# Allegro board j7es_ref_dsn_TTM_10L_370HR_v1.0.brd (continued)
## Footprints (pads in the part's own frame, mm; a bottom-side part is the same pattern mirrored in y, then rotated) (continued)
HTSSOP14_TPS1H100-Q1_180X200_1-2
  rect 1.6x0.305 smd: 1(-2.8,1.95) 2(-2.8,1.3) 3(-2.8,0.65) 4(-2.8,0) 5(-2.8,-0.65) 6(-2.8,-1.3) 7(-2.8,-1.95) 8(2.8,-1.95) 9(2.8,-1.3) 10(2.8,-0.65) 11(2.8,0) 12(2.8,0.65) 13(2.8,1.3) 14(2.8,1.95)
  rect 3.404x5.004 smd: 15(0,0)
IND2-7030D
  rect 2.032x3.81 smd: 1(-2.921,0) 2(2.921,0)
IND2-ATCA-06
  round 2.286 hole 1.219: 1(-7.493,0) 2(7.493,0)
IND2-LQH3N
  rect 1.397x3.048 smd: 1(-1.27,0) 2(1.27,0)
IND1008_1-2
  rect 1.194x2.21 smd: 1(-1.1,0) 2(1.1,0)
IND2520-40X80
  rect 1.016x2.032 smd: 1(-1.118,0) 2(1.118,0)
IND-DFEG10040
  rect 2.997x3.429 smd: 1(-4.445,0) 2(4.445,0)
IND-IHLP2020
  rect 1.778x2.794 smd: 1(-2.413,0) 2(2.413,0)
IND-IHLP5050
  rect 2.921x5.385 smd: 1(-5.588,0) 2(5.588,0)
IND-IHLP-COMBO
  custom 0.724x0.724 smd: 1(-3.607,0) 2(3.607,0)
IND-MSS7341
  rect 2.54x7.112 smd: 1(-2.286,0) 2(2.286,0)
JMP402-25
  rect 0.635x0.635 smd: 1(-0.508,0)
  round 0.635 smd: 2(0.508,0) 3(1.524,0)
JUMP1X2-6040
  rect 1.524x1.524 hole 1.016: 1(0,0)
  round 1.524 hole 1.016: 2(0,-2.54)
L603-35X45
  oval 0.889x1.143 smd: 1(-0.762,0) 2(0.762,0)
LED1206-59X59
  rect 1.499x1.499 smd: 1(-1.753,0) 2(1.753,0)
MHP93-200
  round 5.08 hole 2.362: 1(0,0)
MOLEX-34826-0124
  round 1.524 hole 0.991: 1(-7.01,1.295) 2(-5.004,1.295) 3(5.004,1.295) 4(7.01,1.295) 5(-7.01,-0.914) 6(-5.004,-0.914) 7(-2.997,-0.914) 8(-0.991,-0.914) 9(0.991,-0.914) 10(2.997,-0.914) 11(5.004,-0.914) 12(7.01,-0.914)
  round 3.556 hole 2.54: 13(-9.855,0) 14(9.855,0)
OSC4_ASDMB_100X85_SMD_0-9
  rect 0.66x0.864 smd: 1(-0.825,-0.775) 2(0.825,-0.775) 3(0.825,0.775) 4(-0.825,0.775)
PWP16-14X70-PAD
  oval 0.356x1.778 smd: 1(-2.276,-2.987) 2(-1.626,-2.987) 3(-0.975,-2.987) 4(-0.325,-2.987) 5(0.325,-2.987) 6(0.975,-2.987) 7(1.626,-2.987) 8(2.276,-2.987) 9(2.276,2.987) 10(1.626,2.987) 11(0.975,2.987) 12(0.325,2.987) 13(-0.325,2.987) 14(-0.975,2.987) 15(-1.626,2.987) 16(-2.276,2.987)
  rect 4.572x3.048 smd: 17(0,0)
PWP28-14X70
  oval 0.356x1.778 smd: 1(-4.227,-2.921) 2(-3.576,-2.921) 3(-2.926,-2.921) 4(-2.276,-2.921) 5(-1.626,-2.921) 6(-0.975,-2.921) 7(-0.325,-2.921) 8(0.325,-2.921) 9(0.975,-2.921) 10(1.626,-2.921) 11(2.276,-2.921) 12(2.926,-2.921) 13(3.576,-2.921) 14(4.227,-2.921) 15(4.227,2.921) 16(3.576,2.921) 17(2.926,2.921) 18(2.276,2.921) 19(1.626,2.921) 20(0.975,2.921) 21(0.325,2.921) 22(-0.325,2.921) 23(-0.975,2.921) 24(-1.626,2.921) 25(-2.276,2.921) 26(-2.926,2.921) 27(-3.576,2.921) 28(-4.227,2.921)
  rect 7.62x2.54 smd: 29(0,0)
PWR-Q5A-SLPS319
  rect 0.711x1.397 smd: 1(-1.905,0) 2(-0.635,0) 3(0.635,0) 4(1.905,0)
  custom 1.111x1.111 smd: 5(0,2.781)
QFN64_19-68_360X360_0-9_EP6
  rect 0.838x0.305 smd: 1(-4.5,3.75) 2(-4.5,3.25) 3(-4.5,2.75) 4(-4.5,2.25) 5(-4.5,1.75) 6(-4.5,1.25) 7(-4.5,0.75) 8(-4.5,0.25) 9(-4.5,-0.25) 10(-4.5,-0.75) 11(-4.5,-1.25) 12(-4.5,-1.75) 13(-4.5,-2.25) 14(-4.5,-2.75) 15(-4.5,-3.25) 16(-4.5,-3.75) 33(4.5,-3.75) 34(4.5,-3.25) 35(4.5,-2.75) 36(4.5,-2.25) 37(4.5,-1.75) 38(4.5,-1.25) 39(4.5,-0.75) 40(4.5,-0.25) 41(4.5,0.25) 42(4.5,0.75) 43(4.5,1.25) 44(4.5,1.75) 45(4.5,2.25) 46(4.5,2.75) 47(4.5,3.25) 48(4.5,3.75)
  rect 0.305x0.838 smd: 17(-3.75,-4.5) 18(-3.25,-4.5) 19(-2.75,-4.5) 20(-2.25,-4.5) 21(-1.75,-4.5) 22(-1.25,-4.5) 23(-0.75,-4.5) 24(-0.25,-4.5) 25(0.25,-4.5) 26(0.75,-4.5) 27(1.25,-4.5) 28(1.75,-4.5) 29(2.25,-4.5) 30(2.75,-4.5) 31(3.25,-4.5) 32(3.75,-4.5) 49(3.75,4.5) 50(3.25,4.5) 51(2.75,4.5) 52(2.25,4.5) 53(1.75,4.5) 54(1.25,4.5) 55(0.75,4.5) 56(0.25,4.5) 57(-0.25,4.5) 58(-0.75,4.5) 59(-1.25,4.5) 60(-1.75,4.5) 61(-2.25,4.5) 62(-2.75,4.5) 63(-3.25,4.5) 64(-3.75,4.5)
  rect 5.994x5.994 smd: 65(0,0)
QSH-030-01-F
  round 0.508 hole 1.016 unplated: (-10.061,2.667) (10.061,2.667)
  rect 0.279x2.273 smd: 1(-7.249,-2.865) 2(-7.249,2.865) 3(-6.749,-2.865) 4(-6.749,2.865) 5(-6.248,-2.865) 6(-6.248,2.865) 7(-5.748,-2.865) 8(-5.748,2.865) 9(-5.248,-2.865) 10(-5.248,2.865) 11(-4.75,-2.865) 12(-4.75,2.865) 13(-4.249,-2.865) 14(-4.249,2.865) 15(-3.749,-2.865) 16(-3.749,2.865) 17(-3.249,-2.865) 18(-3.249,2.865) 19(-2.748,-2.865) 20(-2.748,2.865) 21(-2.25,-2.865) 22(-2.25,2.865) 23(-1.75,-2.865) 24(-1.75,2.865) 25(-1.25,-2.865) 26(-1.25,2.865) 27(-0.749,-2.865) 28(-0.749,2.865) 29(-0.249,-2.865) 30(-0.249,2.865) 31(0.249,-2.865) 32(0.249,2.865) 33(0.749,-2.865) 34(0.749,2.865) 35(1.25,-2.865) 36(1.25,2.865) 37(1.75,-2.865) 38(1.75,2.865) 39(2.25,-2.865) 40(2.25,2.865) 41(2.748,-2.865) 42(2.748,2.865) 43(3.249,-2.865) 44(3.249,2.865) 45(3.749,-2.865) 46(3.749,2.865) 47(4.249,-2.865) 48(4.249,2.865) 49(4.75,-2.865) 50(4.75,2.865) 51(5.248,-2.865) 52(5.248,2.865) 53(5.748,-2.865) 54(5.748,2.865) 55(6.248,-2.865) 56(6.248,2.865) 57(6.749,-2.865) 58(6.749,2.865) 59(7.249,-2.865) 60(7.249,2.865)
  rect 2.54x0.432 smd: 61(-8.065,0) 64(8.065,0)
  rect 4.699x0.432 smd: 62(-3.175,0) 63(3.175,0)
R201-6P6SPC
  rect 0.47x0.381 smd: 1(-0.343,0) 2(0.343,0)
R402-25
  round 0.635 smd: 1(-0.508,0) 2(0.508,0)
R603-35X45
  oval 0.889x1.143 smd: 1(-0.762,0) 2(0.762,0)
R0612
  rect 3.175x0.889 smd: 1(0,-0.813) 2(0,0.813)
R1206-40X70
  oval 1.016x1.778 smd: 1(-1.524,0) 2(1.524,0)
RES0201_0-5
  rect 0.457x0.432 smd: 1(-0.33,0) 2(0.33,0)
RES0402_0-5
  rect 0.483x0.508 smd: 1(-0.42,0) 2(0.42,0)
RES0402_1
  rect 0.559x0.635 smd: 1(-0.49,0) 2(0.49,0)
RGE24-11X28-4MM
  rect 0.711x0.279 smd: 1(-1.905,1.245) 2(-1.905,0.747) 3(-1.905,0.249) 4(-1.905,-0.249) 5(-1.905,-0.747) 6(-1.905,-1.245) 13(1.905,-1.245) 14(1.905,-0.747) 15(1.905,-0.249) 16(1.905,0.249) 17(1.905,0.747) 18(1.905,1.245)
  rect 0.279x0.711 smd: 7(-1.245,-1.905) 8(-0.747,-1.905) 9(-0.249,-1.905) 10(0.249,-1.905) 11(0.747,-1.905) 12(1.245,-1.905) 19(1.245,1.905) 20(0.747,1.905) 21(0.249,1.905) 22(-0.249,1.905) 23(-0.747,1.905) 24(-1.245,1.905)
  rect 2.464x2.464 smd: 25(0,0)
RND36-24X10
  oval 0.254x0.61 smd: 1(-2.002,-2.896) 2(-1.501,-2.896) 3(-1.001,-2.896) 4(-0.5,-2.896) 5(0,-2.896) 6(0.498,-2.896) 7(0.998,-2.896) 8(1.499,-2.896) 9(1.999,-2.896) 19(2.002,2.896) 20(1.501,2.896) 21(1.001,2.896) 22(0.5,2.896) 23(0,2.896) 24(-0.498,2.896) 25(-0.998,2.896) 26(-1.499,2.896) 27(-1.999,2.896)
  oval 0.61x0.254 smd: 10(2.896,-2.002) 11(2.896,-1.501) 12(2.896,-1.001) 13(2.896,-0.5) 14(2.896,0) 15(2.896,0.498) 16(2.896,0.998) 17(2.896,1.499) 18(2.896,1.999) 28(-2.896,1.999) 29(-2.896,1.499) 30(-2.896,0.998) 31(-2.896,0.498) 32(-2.896,0) 33(-2.896,-0.5) 34(-2.896,-1.001) 35(-2.896,-1.501) 36(-2.896,-2.002)
  rect 3.81x3.81 smd: 37(0,0)
RTD0064F
  rect 0.6x0.25 smd: 1(-4.4,3.75) 2(-4.4,3.25) 3(-4.4,2.75) 4(-4.4,2.25) 5(-4.4,1.75) 6(-4.4,1.25) 7(-4.4,0.75) 8(-4.4,0.25) 9(-4.4,-0.25) 10(-4.4,-0.75) 11(-4.4,-1.25) 12(-4.4,-1.75) 13(-4.4,-2.25) 14(-4.4,-2.75) 15(-4.4,-3.25) 16(-4.4,-3.75) 33(4.4,-3.75) 34(4.4,-3.25) 35(4.4,-2.75) 36(4.4,-2.25) 37(4.4,-1.75) 38(4.4,-1.25) 39(4.4,-0.75) 40(4.4,-0.25) 41(4.4,0.25) 42(4.4,0.75) 43(4.4,1.25) 44(4.4,1.75) 45(4.4,2.25) 46(4.4,2.75) 47(4.4,3.25) 48(4.4,3.75)
  rect 0.25x0.6 smd: 17(-3.75,-4.4) 18(-3.25,-4.4) 19(-2.75,-4.4) 20(-2.25,-4.4) 21(-1.75,-4.4) 22(-1.25,-4.4) 23(-0.75,-4.4) 24(-0.25,-4.4) 25(0.25,-4.4) 26(0.75,-4.4) 27(1.25,-4.4) 28(1.75,-4.4) 29(2.25,-4.4) 30(2.75,-4.4) 31(3.25,-4.4) 32(3.75,-4.4) 49(3.75,4.4) 50(3.25,4.4) 51(2.75,4.4) 52(2.25,4.4) 53(1.75,4.4) 54(1.25,4.4) 55(0.75,4.4) 56(0.25,4.4) 57(-0.25,4.4) 58(-0.75,4.4) 59(-1.25,4.4) 60(-1.75,4.4) 61(-2.25,4.4) 62(-2.75,4.4) 63(-3.25,4.4) 64(-3.75,4.4)
  rect 5.75x5.75 smd: 65(0,0)
RVC20
  rect 0.279x0.711 smd: 1(-1.245,-1.422) 2(-0.747,-1.422) 3(-0.249,-1.422) 4(0.249,-1.422) 5(0.747,-1.422) 6(1.245,-1.422) 11(1.245,1.422) 12(0.747,1.422) 13(0.249,1.422) 14(-0.249,1.422) 15(-0.747,1.422) 16(-1.245,1.422)
  rect 0.711x0.279 smd: 7(1.905,-0.747) 8(1.905,-0.249) 9(1.905,0.249) 10(1.905,0.747) 17(-1.905,0.747) 18(-1.905,0.249) 19(-1.905,-0.249) 20(-1.905,-0.747)
  rect 2.388x1.6 smd: 21(0,0)
SMA2-78SQ
  rect 1.981x1.981 smd: 1(-2.007,0) 2(2.007,0)
SMC-80X128
  rect 2.032x3.251 smd: 1(-3.124,0) 2(3.124,0)
SO8-25X75-295
  oval 0.635x2.54 smd: 1(-1.905,-3.086) 2(-0.635,-3.086) 3(0.635,-3.086) 4(1.905,-3.086) 5(1.905,3.086) 6(0.635,3.086) 7(-0.635,3.086) 8(-1.905,3.086)
SO14-25X75
  oval 0.635x1.905 smd: 1(-3.81,-2.794) 2(-2.54,-2.794) 3(-1.27,-2.794) 4(0,-2.794) 5(1.27,-2.794) 6(2.54,-2.794) 7(3.81,-2.794) 8(3.81,2.794) 9(2.54,2.794) 10(1.27,2.794) 11(0,2.794) 12(-1.27,2.794) 13(-2.54,2.794) 14(-3.81,2.794)
SOD323
  rect 1.092x0.508 smd: 1(-1.194,0) 2(1.194,0)
SOD523
  rect 0.762x0.381 smd: 1(0.838,0) 2(-0.838,0)
SOT23-5
  rect 0.635x1.016 smd: 1(-0.953,-1.295) 2(0,-1.295) 3(0.953,-1.295) 4(0.953,1.295) 5(-0.953,1.295)
SOT23-28X44-GSD
  rect 0.711x1.118 smd: D(0,1.067) G(-0.965,-1.067) S(0.965,-1.067)
SOT23-123_1-2
  rect 0.838x0.61 smd: 1(-1.05,0.95) 2(-1.05,-0.95) 3(1.05,0)
SOT363-16X45
  rect 0.406x0.635 smd: 1(-0.65,-0.978) 2(0,-0.978) 3(0.65,-0.978) 4(0.65,0.978) 5(0,0.978) 6(-0.65,0.978)
SSOP-16
  oval 0.356x1.778 smd: 1(-2.223,-2.692) 2(-1.587,-2.692) 3(-0.953,-2.692) 4(-0.318,-2.692) 5(0.318,-2.692) 6(0.953,-2.692) 7(1.587,-2.692) 8(2.223,-2.692) 9(2.223,2.692) 10(1.587,2.692) 11(0.953,2.692) 12(0.318,2.692) 13(-0.318,2.692) 14(-0.953,2.692) 15(-1.587,2.692) 16(-2.223,2.692)
SW4-7914G
  rect 1.27x1.778 smd: 1(1.27,2.769) 2(1.27,-2.769) 3(-1.27,2.769) 4(-1.27,-2.769)
TP1-18RD8
  round 0.457 hole 0.203: 1(0,0)
TP1-70X135
  rect 2.286x3.937 smd: 1(0,0)
TP40_SMD
  round 1.016 smd: 1(0,0)
TP-30RD13
  round 0.762 hole 0.33: 1(0,0)
TPBGA24_39-37_240X320_1-2
  round 0.356 smd: A2(-1,2) A3(0,2) A4(1,2) A5(2,2) B1(-2,1) B2(-1,1) B3(0,1) B4(1,1) B5(2,1) C1(-2,0) C2(-1,0) C3(0,0) C4(1,0) C5(2,0) D1(-2,-1) D2(-1,-1) D3(0,-1) D4(1,-1) D5(2,-1) E1(-2,-2) E2(-1,-2) E3(0,-2) E4(1,-2) E5(2,-2)
TSDSON8
  custom 0.248x0.248 smd: 1(-0.33,-1.499)
  rect 0.356x1.016 smd: 4(0.978,-1.486)
  custom 0.572x0.572 smd: 5(0,0.673)
unnamed#2
  round 6.223 hole 6.35 unplated: (0,0)
unnamed#3
  rect 0.508x0.305 smd: 1(-0.612,0.275) 2(-0.612,-0.275) 3(0.612,-0.275) 4(0.612,0.275)
unnamed#4
  rect 0.483x0.508 smd: 1(-0.42,0) 2(0.42,0)
VQFN56_19-68_320X320_0-9_EP6
  rect 0.787x0.305 smd: 1(-4,3.25) 2(-4,2.75) 3(-4,2.25) 4(-4,1.75) 5(-4,1.25) 6(-4,0.75) 7(-4,0.25) 8(-4,-0.25) 9(-4,-0.75) 10(-4,-1.25) 11(-4,-1.75) 12(-4,-2.25) 13(-4,-2.75) 14(-4,-3.25) 29(4,-3.25) 30(4,-2.75) 31(4,-2.25) 32(4,-1.75) 33(4,-1.25) 34(4,-0.75) 35(4,-0.25) 36(4,0.25) 37(4,0.75) 38(4,1.25) 39(4,1.75) 40(4,2.25) 41(4,2.75) 42(4,3.25)
  rect 0.305x0.787 smd: 15(-3.25,-4) 16(-2.75,-4) 17(-2.25,-4) 18(-1.75,-4) 19(-1.25,-4) 20(-0.75,-4) 21(-0.25,-4) 22(0.25,-4) 23(0.75,-4) 24(1.25,-4) 25(1.75,-4) 26(2.25,-4) 27(2.75,-4) 28(3.25,-4) 43(3.25,4) 44(2.75,4) 45(2.25,4) 46(1.75,4) 47(1.25,4) 48(0.75,4) 49(0.25,4) 50(-0.25,4) 51(-0.75,4) 52(-1.25,4) 53(-1.75,4) 54(-2.25,4) 55(-2.75,4) 56(-3.25,4)
  rect 5.588x5.588 smd: 57(0,0)
WFBGA200_MT53DDS_400X570_1
  round 0.356 smd: A1(-4.4,6.825) A2(-3.6,6.825) A3(-2.8,6.825) A4(-2,6.825) A5(-1.2,6.825) A8(1.2,6.825) A9(2,6.825) A10(2.8,6.825) A11(3.6,6.825) A12(4.4,6.825) AA1(-4.4,-6.175) AA2(-3.6,-6.175) AA3(-2.8,-6.175) AA4(-2,-6.175) AA5(-1.2,-6.175) AA8(1.2,-6.175) AA9(2,-6.175) AA10(2.8,-6.175) AA11(3.6,-6.175) AA12(4.4,-6.175) AB1(-4.4,-6.825) AB2(-3.6,-6.825) AB3(-2.8,-6.825) AB4(-2,-6.825) AB5(-1.2,-6.825) AB8(1.2,-6.825) AB9(2,-6.825) AB10(2.8,-6.825) AB11(3.6,-6.825) AB12(4.4,-6.825) B1(-4.4,6.175) B2(-3.6,6.175) B3(-2.8,6.175) B4(-2,6.175) B5(-1.2,6.175) B8(1.2,6.175) B9(2,6.175) B10(2.8,6.175) B11(3.6,6.175) B12(4.4,6.175) C1(-4.4,5.525) C2(-3.6,5.525) C3(-2.8,5.525) C4(-2,5.525) C5(-1.2,5.525) C8(1.2,5.525) C9(2,5.525) C10(2.8,5.525) C11(3.6,5.525) C12(4.4,5.525) D1(-4.4,4.875) D2(-3.6,4.875) D3(-2.8,4.875) D4(-2,4.875) D5(-1.2,4.875) D8(1.2,4.875) D9(2,4.875) D10(2.8,4.875) D11(3.6,4.875) D12(4.4,4.875) E1(-4.4,4.225) E2(-3.6,4.225) E3(-2.8,4.225) E4(-2,4.225) E5(-1.2,4.225) E8(1.2,4.225) E9(2,4.225) E10(2.8,4.225) E11(3.6,4.225) E12(4.4,4.225) F1(-4.4,3.575) F2(-3.6,3.575) F3(-2.8,3.575) F4(-2,3.575) F5(-1.2,3.575) F8(1.2,3.575) F9(2,3.575) F10(2.8,3.575) F11(3.6,3.575) F12(4.4,3.575) G1(-4.4,2.925) G2(-3.6,2.925) G3(-2.8,2.925) G4(-2,2.925) G5(-1.2,2.925) G8(1.2,2.925) G9(2,2.925) G10(2.8,2.925) G11(3.6,2.925) G12(4.4,2.925) H1(-4.4,2.275) H2(-3.6,2.275) H3(-2.8,2.275) H4(-2,2.275) H5(-1.2,2.275) H8(1.2,2.275) H9(2,2.275) H10(2.8,2.275) H11(3.6,2.275) H12(4.4,2.275) J1(-4.4,1.625) J2(-3.6,1.625) J3(-2.8,1.625) J4(-2,1.625) J5(-1.2,1.625) J8(1.2,1.625) J9(2,1.625) J10(2.8,1.625) J11(3.6,1.625) J12(4.4,1.625) K1(-4.4,0.975) K2(-3.6,0.975) K3(-2.8,0.975) K4(-2,0.975) K5(-1.2,0.975) K8(1.2,0.975) K9(2,0.975) K10(2.8,0.975) K11(3.6,0.975) K12(4.4,0.975) N1(-4.4,-0.975) N2(-3.6,-0.975) N3(-2.8,-0.975) N4(-2,-0.975) N5(-1.2,-0.975) N8(1.2,-0.975) N9(2,-0.975) N10(2.8,-0.975) N11(3.6,-0.975) N12(4.4,-0.975) P1(-4.4,-1.625) P2(-3.6,-1.625) P3(-2.8,-1.625) P4(-2,-1.625) P5(-1.2,-1.625) P8(1.2,-1.625) P9(2,-1.625) P10(2.8,-1.625) P11(3.6,-1.625) P12(4.4,-1.625) R1(-4.4,-2.275) R2(-3.6,-2.275) R3(-2.8,-2.275) R4(-2,-2.275) R5(-1.2,-2.275) R8(1.2,-2.275) R9(2,-2.275) R10(2.8,-2.275) R11(3.6,-2.275) R12(4.4,-2.275) T1(-4.4,-2.925) T2(-3.6,-2.925) T3(-2.8,-2.925) T4(-2,-2.925) T5(-1.2,-2.925) T8(1.2,-2.925) T9(2,-2.925) T10(2.8,-2.925) T11(3.6,-2.925) T12(4.4,-2.925) U1(-4.4,-3.575) U2(-3.6,-3.575) U3(-2.8,-3.575) U4(-2,-3.575) U5(-1.2,-3.575) U8(1.2,-3.575) U9(2,-3.575) U10(2.8,-3.575) U11(3.6,-3.575) U12(4.4,-3.575) V1(-4.4,-4.225) V2(-3.6,-4.225) V3(-2.8,-4.225) V4(-2,-4.225) V5(-1.2,-4.225) V8(1.2,-4.225) V9(2,-4.225) V10(2.8,-4.225) V11(3.6,-4.225) V12(4.4,-4.225) W1(-4.4,-4.875) W2(-3.6,-4.875) W3(-2.8,-4.875) W4(-2,-4.875) W5(-1.2,-4.875) W8(1.2,-4.875) W9(2,-4.875) W10(2.8,-4.875) W11(3.6,-4.875) W12(4.4,-4.875) Y1(-4.4,-5.525) Y2(-3.6,-5.525) Y3(-2.8,-5.525) Y4(-2,-5.525) Y5(-1.2,-5.525) Y8(1.2,-5.525) Y9(2,-5.525) Y10(2.8,-5.525) Y11(3.6,-5.525) Y12(4.4,-5.525)
WSON8_19-68_80X80_0-8
  rect 0.711x0.305 smd: 1(-1.05,0.75) 2(-1.05,0.25) 3(-1.05,-0.25) 4(-1.05,-0.75) 5(1.05,-0.75) 6(1.05,-0.25) 7(1.05,0.25) 8(1.05,0.75)
  rect 0.991x1.702 smd: 9(0,0)
XTAL4-ABM11
  rect 0.889x0.813 smd: 1(-0.711,-0.559) 2(0.711,-0.559) 3(0.711,0.559) 4(-0.711,0.559)
XTAL4_ABM10W_100X80_SMD_0-6
  rect 1.194x0.838 smd: 1(-0.813,-0.6) 2(0.813,-0.6) 3(0.813,0.6) 4(-0.813,0.6)
XTAL_ABS07AIG_130X60_SMD_0-9
  rect 0.991x1.803 smd: 1(-1.275,0) 2(1.275,0)
XTAL_ECS-32_130X60_SMD_0-9
  rect 1.118x1.905 smd: 1(-1.25,0) 2(1.25,0)

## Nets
1V8_RSTOUTN: R1192.1 U1017.M5(RSTN) U1033.4(O)
DGND: C26.2 C27.2 C28.2 C29.2 C30.2 C31.2 C32.2(GND) C33.2(GND) C34.2 C35.2 C37.2(GND) C38.2(GND) C41.2(GND) C42.2(GND) C43.2 C44.2 C45.2 C46.2 C47.2 C48.2 C49.2 C50.2 C53.2(GND) C54.2(GND) C55.2 C56.2 C57.2(GND) C58.2(GND) C59.2(GND) C60.2 C61.2 C62.2 C63.2 C64.2(GND) C65.2(GND) C66.2(GND) C67.2(GND) C68.2(GND) C69.2(GND) C70.2(GND) C71.2 C72.2 C73.2 C78.2(GND) C79.2 C80.2(GND) C81.2 C82.2 C83.2 C84.2(GND) C85.2 C86.2 C87.2 C88.2 C89.2 C90.2 C91.2(GND) C92.2 C93.2(GND) C94.2 C95.2(GND) C96.2 C97.2 C98.2(GND) C99.2(GND) C100.2(GND) C101.2 C102.2 C104.2 C105.2 C106.2(GND) C107.2(GND) C110.2 C111.2 C112.2 C114.2 C118.2(GND) C119.2(GND) C120.2 C121.2 C122.2 C124.2 C125.2 C128.2 C130.2 C131.2 C132.2 C133.2 C135.2 C136.2 C141.2 C149.2(GND) C155.2 C156.2 C157.2 C158.2 C159.2 C160.2(GND) C161.2(GND) C162.2 C163.2 C164.2 C165.2 C166.2(GND) C167.2(GND) C168.2(GND) C169.2 C173.2 C177.2 C178.2 C179.2(GND) C180.2(GND) C181.2(GND) C182.2(GND) C184.2(GND) C185.2 C186.2 C187.2 C188.2 C189.2 C190.2 C192.2(GND) C193.2(GND) C197.2(GND) C198.2(GND) C199.2 C200.2 C201.2 C202.2 C203.2 C204.2 C205.2 C206.2 C208.2 C210.2 C211.2 C228.2 C234.2 C236.2 C237.2 C238.2 C239.2 C242.2 C243.2 C244.2 C245.2 C246.2 C247.2 C249.2 C252.2 C253.2 C254.2 C255.2 C256.2 C257.2 C258.2 C259.2 C260.2(GND) C261.2 C262.2 C263.2 C264.2 C265.2 C266.2 C267.2 C268.2 C269.2 C270.2 C271.2 C272.2(GND) C273.2 C274.2 C275.2 C276.2 C277.2 C278.2 C279.2 C280.2 C281.2 C282.2 C283.2 C284.2 C285.2 C286.2 C287.2 C288.2 C289.2 C290.2 C291.2 C292.2 C293.2 C294.2 C295.2 C296.2 C297.2 C298.2 C299.2 C300.2 C301.2 C302.2 C303.2 C304.2 C305.2 C306.2 C307.2 C308.2 C309.2 C310.2 C311.2 C312.2 C313.2 C314.2 C315.2 C316.2 C317.2 C318.2 C319.2 C320.2 C321.2 C322.2 C323.2 C324.2 C325.2 C326.2 C327.2 C328.2 C329.2 C330.2 C331.2 C332.2 C333.2 C334.2 C335.2 C336.2 C337.2 C338.2 C339.2 C340.2 C341.2 C342.2 C343.2 C344.2 C345.2 C346.2 C348.2 C349.2 C350.2 C351.2 C352.2 C353.2 C354.2 C355.2 C356.2 C357.2 C358.2 C359.2 C360.2 C361.2 C362.2 C363.2 C364.2 C365.2 C366.2 C367.2 C368.2 C369.2 C370.2 C371.2 C372.2 C373.2 C374.2 C375.2 C376.2 C377.2 C378.2 C379.2 C380.2 C381.2 C382.2 C383.2 C384.2 C385.2 C386.2 C387.2 C388.2 C389.2 C390.2 C391.2 C392.2 C393.2 C394.2 C395.2 C396.2 C397.2 C398.2 C399.2 C400.2 C402.2 C403.2 C404.2 C405.2 C410.2 C411.2 C413.2 C425.2 C427.2 C428.2 C429.2 C430.2 C431.2 C432.2 C433.2 C434.2 C435.2 C436.2 C437.2 C438.2 C439.2 C440.2 C441.2 C442.2 C443.2 C444.2 C445.2 C446.2 C449.2 C450.2 C451.2 C452.2 C453.2 C481.2 C482.2 C483.2 C484.2 C485.2 C486.2 C487.2 C488.2 C489.2 C490.2 C491.2 C492.2 C493.2 C494.2 C495.2 C496.2 C497.2 C498.2 C499.2 C500.2 C501.2 C502.2 C503.1 C504.2 C505.2 C506.1 C507.2 C508.2 C509.2 C510.2 C511.2 C512.2 C513.2 C514.2 C516.2 C517.2 C518.2 C519.2 C520.2 C521.2 C522.2 C523.2 C524.2 C525.2 C526.2 C527.2 C528.2 C529.2 C530.2 C531.2 C532.2 C533.2 C534.2 C535.2 C536.2 C537.2 C538.2 C539.2 C540.2 C541.2 C542.2 C543.2 C544.2 C545.2 C546.2 C570.2 C571.2 C1003.1 C1004.2 C1005.2 C1006.1 C1007.1 C1008.2 C1009.2 C1010.2 C1011.2 C1012.2 C1015.1 C1016.2 C1017.2 C1018.2 C1019.2 C1020.2 C1021.2 C1022.2 C1023.2 C1024.2 C1026.2 C1027.1 C1028.2 C1030.2 C1031.2 C1032.2 C1034.2 C1035.2 C1036.2 C1038.2 C1039.1 C1040.2 C1041.1 C1043.2 C1044.2 C1045.2 C1047.1 C1050.1 C1051.2 C1052.1 C1055.2 C1059.1 C1060.2 C1061.1 C1062.1 C1063.2 C1064.2 C1065.2 C1069.2 C1070.2 C1136.2 C1145.2 C1146.2 C1182.2 C1183.2 C1187.2 C1190.2 C1197.2 C1198.2 C1199.2 C1201.2 C1202.2 C1205.2 C1209.1 C1238.2 C1239.2 C1240.2 C1241.2 C1242.2 C1245.1 C1249.2 C2023.2 C2027.2 C2034.2 C2035.1 C2037.2 C2084.2 C2085.2 C2086.2 C2087.2 C2115.2 C2116.2 C2117.2 C2118.2 C2119.2 C2120.2 C2121.2 C2122.2 C2123.2 C2124.2 C2125.2 C2126.2 C2127.2 C2128.2 C2129.2 C3049.2 C3050.2 C3051.2 C3052.2 C3053.2 C3054.2 C3056.2 C3057.2 C3058.2 C3061.2 C3062.2 C3063.2 C3067.2 C3068.2 C3069.2 C3070.2 C3071.2 C3096.2 C3097.2 C3098.2 C3100.2 C3101.2 C3102.2 C3103.2 C3105.2 C3106.2 C3107.2 C3108.1 C3109.1 C3110.2 C3111.2 C3114.2 C3116.2 C3118.2 C3122.1 C3123.2 C3126.2 C3127.2 C3128.2 C3129.2 C3130.2 C3133.2 C3134.2 C3135.2 C3136.2 C3139.2 C3140.2 C3141.2 C3142.2 C3145.2 C3146.2 C3147.2 C3148.2 C3149.2 D1.1(A) D2.2(ANODE) D1006.2(ANODE) D1018.1(CATHODE) D1020.2(ANODE) D3019.2(GND) D3020.2(GND) D3021.2(GND) D3022.2(GND) D3029.2(GND) D3030.2(GND) D3031.2(GND) D3032.2(GND) D3033.2(GND) D3034.2(GND) D3036.2(ANODE) DS1000.1(CATHODE) FL3026.2(GND1) J1000.4(GND4) J1000.7(GND8) J1000.G1 J1000.G2 J1001.4(GND4) J1001.7(GND8) J1001.G1 J1001.G2 J1003.3 J1003.4 J1010.2 J1011.16(GND16) J1011.57(GND57) J1011.58(GND58) J1011.61(GNDCT1) J1011.62(GNDCT2) J1011.63(GNDCT3) J1011.64(GNDCT4) J3003.2(GND#2) J3003.5(GND#5) J3003.8(GND#8) J3003.11(GND#11) J3003.16(GND#16) J3003.19(RETURN) J3003.SH1 J3003.SH2 J3003.SH3 J3003.SH4 J3005.4 J3005.SH1 J3005.SH2 J3005.SH3 J3005.SH4 JZ2000.5 JZ2000.6 JZ2000.11 JZ2000.12 M1000.1 M1001.1 P5.2 P5.3 P5.4 P5.5 P6.2 P6.3 P6.4 P6.5 P7.2 P7.3 P7.4 P7.5 P8.2 P8.3 P8.4 P8.5 Q13.S Q1001.1(S2) Q1008.1(S) R1.2 R46.1 R80.2 R87.2 R113.2 R124.2 R169.1 R201.2 R202.2 R203.2 R204.1 R205.2 R206.2 R207.2 R208.2 R210.2 R213.2 R214.2 R216.2 R218.2 R225.2 R227.2 R228.2 R233.2 R234.2 R235.2 R236.2 R237.2 R238.2 R253.2 R515.1 R522.1 R1003.2 R1004.2 R1005.2 R1009.2 R1011.2 R1016.2 R1019.2 R1025.1 R1029.1 R1030.2 R1032.1 R1041.1 R1042.2 R1045.2 R1046.2 R1072.1 R1108.2 R1109.2 R1126.1 R1132.2 R1133.2 R1143.2 R1147.1 R1152.2 R1164.2 R1205.1 R1221.2 R2032.1 R2103.1 R2105.1 R2107.2 R3058.2 R3059.2 R3060.2 R3062.1 R3067.2 R3103.1 R3110.2 R3111.2 R3112.2 R3118.2 R3119.2 R3121.1 R3122.2 R3123.2 R3124.2 R3128.2 R3131.2 R3134.2 R3141.2 R3146.1 R3149.2 R3151.2 RJ1000.3 RJ2008.3 SW2001.1(A) SW2001.2(AA) TP1016.1 U6.5(GND) U6.9(EP) U9.A7(VSS#A7) U9.A10(VSS#A10) U9.A13(VSS#A13) U9.A16(VSS#A16) U9.A19(VSS#A19) U9.A22(VSS#A22) U9.AA7(VSS#AA7) U9.AA9(VSS#AA9) U9.AA11(VSS#AA11) U9.AA13(VSS#AA13) U9.AA14(VSS#AA14) U9.AA16(VSS#AA16) U9.AA18(VSS#AA18) U9.AB8(VSS#AB8) U9.AB17(VSS#AB17) U9.AB19(VSS#AB19) U9.AB20(VSS#AB20) U9.AB22(VSS#AB22) U9.AC10(VSS#AC10) U9.AC13(VSS#AC13) U9.AC16(VSS#AC16) U9.AD11(VSS#AD11) U9.AD14(VSS#AD14) U9.AD17(VSS#AD17) U9.AE7(VSS#AE7) U9.AE10(VSS#AE10) U9.AE12(VSS#AE12) U9.AE15(VSS#AE15) U9.AE16(VSS#AE16) U9.AE19(VSS#AE19) U9.AF5(VSS#AF5) U9.AF8(VSS#AF8) U9.AF11(VSS#AF11) U9.AF14(VSS#AF14) U9.AF17(VSS#AF17) U9.AF20(VSS#AF20) U9.AF25(VSS#AF25) U9.AG4(VSS#AG4) U9.AG7(VSS#AG7) U9.AG10(VSS#AG10) U9.AG13(VSS#AG13) U9.AG16(VSS#AG16) U9.AG19(VSS#AG19) U9.AH2(VSS#AH2) U9.AH5(VSS#AH5) U9.AH8(VSS#AH8) U9.AH11(VSS#AH11) U9.AH14(VSS#AH14) U9.AH17(VSS#AH17) U9.AH20(VSS#AH20) U9.AJ4(VSS#AJ4) U9.AJ7(VSS#AJ7) U9.AJ10(VSS#AJ10) U9.AJ13(VSS#AJ13) U9.AJ16(VSS#AJ16) U9.AJ19(VSS#AJ19) U9.B3(VSS#B3) U9.B6(VSS#B6) U9.B9(VSS#B9) U9.B12(VSS#B12) U9.B15(VSS#B15) U9.B18(VSS#B18) U9.B21(VSS#B21) U9.C1(VSS#C1) U9.C5(VSS#C5) U9.C8(VSS#C8) U9.C11(VSS#C11) U9.C14(VSS#C14) U9.C17(VSS#C17) U9.C20(VSS#C20) U9.D2(VSS#D2) U9.D4(VSS#D4) U9.D7(VSS#D7) U9.D10(VSS#D10) U9.D13(VSS#D13) U9.D16(VSS#D16) U9.D19(VSS#D19) U9.E1(VSS#E1) U9.E5(VSS#E5) U9.E9(VSS#E9) U9.E12(VSS#E12) U9.E15(VSS#E15) U9.F4(VSS#F4) U9.F8(VSS#F8) U9.F14(VSS#F14) U9.G1(VSS#G1) U9.G7(VSS#G7) U9.G11(VSS#G11) U9.G13(VSS#G13) U9.G15(VSS#G15) U9.G17(VSS#G17) U9.H4(VSS#H4) U9.H6(VSS#H6) U9.H8(VSS#H8) U9.H10(VSS#H10) U9.H12(VSS#H12) U9.H14(VSS#H14) U9.H16(VSS#H16) U9.H18(VSS#H18) U9.H20(VSS#H20) U9.J7(VSS#J7) U9.J9(VSS#J9) U9.J11(VSS#J11) U9.J13(VSS#J13) U9.J15(VSS#J15) U9.J17(VSS#J17) U9.J21(VSS#J21) U9.J23(VSS#J23) U9.K1(VSS#K1) U9.K4(VSS#K4) U9.K8(VSS#K8) U9.K10(VSS#K10) U9.K12(VSS#K12) U9.K14(VSS#K14) U9.K16(VSS#K16) U9.K18(VSS#K18) U9.K20(VSS#K20) U9.K22(VSS#K22) U9.L3(VSS#L3) U9.L7(VSS#L7) U9.L9(VSS#L9) U9.L13(VSS#L13) U9.L15(VSS#L15) U9.L17(VSS#L17) U9.L19(VSS#L19) U9.L21(VSS#L21) U9.L23(VSS#L23) U9.M1(VSS#M1) U9.M4(VSS#M4) U9.M6(VSS#M6) U9.M8(VSS#M8) U9.M10(VSS#M10) U9.M14(VSS#M14) U9.M16(VSS#M16) U9.M18(VSS#M18) U9.M20(VSS#M20) U9.M28(VSS#M28) U9.N3(VSS#N3) U9.N7(VSS#N7) U9.N15(VSS#N15) U9.N17(VSS#N17) U9.N19(VSS#N19) U9.N21(VSS#N21) U9.N27(VSS#N27) U9.N29(VSS#N29) U9.P1(VSS#P1) U9.P4(VSS#P4) U9.P8(VSS#P8) U9.P10(VSS#P10) U9.P12(VSS#P12) U9.P14(VSS#P14) U9.P16(VSS#P16) U9.P18(VSS#P18) U9.P20(VSS#P20) U9.P28(VSS#P28) U9.R3(VSS#R3) U9.R7(VSS#R7) U9.R9(VSS#R9) U9.R13(VSS#R13) U9.R15(VSS#R15) U9.R17(VSS#R17) U9.R19(VSS#R19) U9.T8(VSS#T8) U9.T10(VSS#T10) U9.T14(VSS#T14) U9.T16(VSS#T16) U9.T18(VSS#T18) U9.T21(VSS#T21) U9.U5(VSS#U5) U9.U9(VSS#U9) U9.U15(VSS#U15) U9.U17(VSS#U17) U9.U19(VSS#U19) U9.U21(VSS#U21) U9.V8(VSS#V8) U9.V10(VSS#V10) U9.V12(VSS#V12) U9.V14(VSS#V14) U9.V18(VSS#V18) U9.W9(VSS#W9) U9.W11(VSS#W11) U9.W13(VSS#W13) U9.W16(VSS#W16) U9.W20(VSS#W20) U9.Y8(VSS#Y8) U9.Y10(VSS#Y10) U9.Y12(VSS#Y12) U9.Y15(VSS#Y15) U9.Y17(VSS#Y17) U9.Y19(VSS#Y19) U9.Y21(VSS#Y21) U11.A3(VSS#A3) U11.A10(VSS#A10) U11.AB3(VSS#AB3) U11.AB5(VSS#AB5) U11.AB8(VSS#AB8) U11.AB10(VSS#AB10) U11.C1(VSS#C1) U11.C5(VSS#C5) U11.C8(VSS#C8) U11.C12(VSS#C12) U11.D2(VSS#D2) U11.D4(VSS#D4) U11.D9(VSS#D9) U11.D11(VSS#D11) U11.E1(VSS#E1) U11.E5(VSS#E5) U11.E8(VSS#E8) U11.E12(VSS#E12) U11.G1(VSS#G1) U11.G3(VSS#G3) U11.G5(VSS#G5) U11.G8(VSS#G8) U11.G10(VSS#G10) U11.G12(VSS#G12) U11.J1(VSS#J1) U11.J3(VSS#J3) U11.J10(VSS#J10) U11.J12(VSS#J12) U11.K2(VSS#K2) U11.K4(VSS#K4) U11.K9(VSS#K9) U11.K11(VSS#K11) U11.N2(VSS#N2) U11.N4(VSS#N4) U11.N9(VSS#N9) U11.N11(VSS#N11) U11.P1(VSS#P1) U11.P3(VSS#P3) U11.P10(VSS#P10) U11.P12(VSS#P12) U11.T1(VSS#T1) U11.T3(VSS#T3) U11.T5(VSS#T5) U11.T8(VSS#T8) U11.T10(VSS#T10) U11.T12(VSS#T12) U11.V1(VSS#V1) U11.V5(VSS#V5) U11.V8(VSS#V8) U11.V12(VSS#V12) U11.W2(VSS#W2) U11.W4(VSS#W4) U11.W9(VSS#W9) U11.W11(VSS#W11) U11.Y1(VSS#Y1) U11.Y5(VSS#Y5) U11.Y8(VSS#Y8) U11.Y12(VSS#Y12) U18.3(GND) U22.5(GND) U22.9(EP) U24.B3(VSS#B3) U24.C1(VSS#C1) U24.E5(VSS#E5) U27.5(REFGND1) U27.6(REFGND2) U27.21(FB_B2) U27.36(VBACKUP) U27.57(GND) U29.5(REFGND1) U29.6(REFGND2) U29.21(FB_B2) U29.36(VBACKUP) U29.38(OSC32KIN) U29.57(GND) U129.3(GND) U130.3(GND) U131.3(GND) U1000.3(GND#3) U1000.8(GND#8) U1001.11(GND) U1001.21(PAD) U1002.4(GND#4) U1002.13(GND#13) U1005.10(AGND) U1005.15(PGND#15) U1005.16(PGND#16) U1005.17(TPAD) U1007.3(AGND) U1007.9(PGND) U1007.25(DAP) U1008.10(AGND) U1008.13(ISNS(-)) U1008.14(ISNS(+)) U1008.22(PGND) U1008.29(PAD) U1011.1(A0) U1011.2(A1) U1011.3(NC) U1011.4(VSS) U1017.G2(VSS.1) U1017.G3(VSS.2) U1017.G4(VSS.3) U1017.G5(VSS.4) U1017.G6(VSS.5) U1017.G7(VSS.6) U1017.G8(VSS.7) U1017.G9(VSS.8) U1017.H2(VSSQ.1) U1017.H9(VSSQ.2) U1017.J5(VSS.9) U1017.L3(VSSQ.3) U1017.L8(VSSQ.4) U1017.M4(VSSQ.5) U1017.M7(VSSQ.6) U1017.P2(VSSQ.7) U1017.P9(VSSQ.8) U1022.1(GND) U1022.9(PAD) U1027.6(AGND) U1027.8(PGND) U1027.9(PAD) U1033.2(I) U1033.3(GND) U2007.2(GND) U2010.2(GND) U2011.37(GND) U2012.2(GND) U2023.5(GND) U2023.7(PAD) U3011.2(GND) U3011.15(EP) U3019.1(DSI1_D2N) U3019.2(DSI1_D2P) U3019.3(DSI1_D1N) U3019.4(DSI1_D1P) U3019.5(DSI1_D0N) U3019.6(DSI1_D0P) U3019.7(DSI1_CLKN) U3019.8(DSI1_CLKP) U3019.29(RES0) U3019.40(RES1) U3019.62(DSI1_D3N) U3019.63(DSI1_D3P) U3019.65(GND) U3020.2(GND) U3021.3(GND#3) U3021.8(GND#8) U3022.65(DAP) Y1.2(GND1) Y1.4(GND2) Y3.2(GND1) Y3.4(GND2) Y2000.2(GND1) Y2000.4(GND2)
V3V3_DP0: C3116.1 C3118.1 J3003.20(PWR)
VBAT: J1003.1 J1003.2 R1012.1
VBAT_A: C1060.1 L1003.2 TP1004.1(TP)
VBAT_F: C1030.1 C1031.1 C1055.1 D1008.2(ANODE) L1004.2 Q1005.5(D) R1037.1 TP1013.1(TP)
VBAT_PM: C1023.1 D1002.ANODE1 D1002.ANODE2 D1019.1(CATHODE) Q1002.1(S1) Q1002.2(S2) Q1002.3(S3) R1012.2 U1006.4(ANODE)
VBAT_SYS: C1019.1 C1028.1 C1035.1 C1036.1 C2115.1 L1000.2 Q1007.5(D) R1142.2 RJ2008.1 TP1000.1(TP) U1007.15(VIN) U2007.10(VSUP)
VBUS_USBC_CONN: C1003.2 C1004.1 C1009.1 J1000.1(VBUS) R171.1 R1000.1 U1001.15(OUT#15) U1001.16(OUT#16)
VCC_12V0: C3050.1 C3053.1 U3011.8(VS#8) U3011.9(VS#9) U3011.10(VS#10)
VCC_12V_DSI0: C3122.2 C3123.1 D3036.1(CATHODE) J3005.2 TP3006.1(TP) U3011.5(OUT1) U3011.6(OUT2) U3011.7(OUT3)
VCC_LM5141: C1043.1 D1004.2(ANODE) U1007.10(VCC)
VCC_LM5175: C1040.1 D1005.2(A) D1007.2(A) R1040.2 U1008.23(VCC)
VCCA_3V3: C203.1 C210.1 C481.1 C484.1 C485.1 C486.1 C487.1 C488.1 C489.1 C490.1 C491.1 C492.1 C493.1 C497.1 C498.1 C501.1 C516.1 C519.1 C520.1 C521.1 C522.1 C523.1 C524.1 C525.1 C526.1 C527.1 C528.1 C531.1 C532.1 C533.1 C3146.1 C3147.1 C3148.1 C3149.1 U22.1(VIN1) U22.2(VIN2) U22.4(VBIAS) U27.4(VCCA) U27.8(PVIN_LDO4) U27.10(PVIN_LDO3) U27.12(PVIN_LDO12) U27.17(PVIN_B2) U27.26(PVIN_B1) U27.35(PVIN_B5) U27.45(PVIN_B3) U27.54(PVIN_B4) U29.4(VCCA) U29.8(PVIN_LDO4) U29.10(PVIN_LDO3) U29.12(PVIN_LDO12) U29.17(PVIN_B2) U29.26(PVIN_B1) U29.35(PVIN_B5) U29.45(PVIN_B3) U29.54(PVIN_B4) U103.1(S1) U103.2(S2) U103.3(S3)
VDD1_LPDDR4_1V8: C288.1 C289.1 C301.1 C312.1 C341.1 C345.1 C386.1 C388.1 C394.1 C398.1 C400.1 C514.1 U11.F1(VDD1#F1) U11.F12(VDD1#F12) U11.G4(VDD1#G4) U11.G9(VDD1#G9) U11.T4(VDD1#T4) U11.T9(VDD1#T9) U11.U1(VDD1#U1) U11.U12(VDD1#U12) U27.13(VOUT_LDO1)
VDD18_DSI: C3051.1 C3052.1 C3100.1 C3111.1 FL3011.2 R3065.1 R3066.1 R3113.1 U3019.24(VDD18#24) U3019.61(VDD18#61)
VDD_1P0: C2086.1 C2087.1 L2017.2 R2058.2 R2059.2
VDD_CORE_0V8: C26.1 C27.1 C28.1 C29.1 C41.1(INPUT) C41.3(OUTPUT) C42.1(INPUT) C42.3(OUTPUT) C53.1(INPUT) C53.3(OUTPUT) C54.1(INPUT) C54.3(OUTPUT) C59.1(INPUT) C59.3(OUTPUT) C60.1 C61.1 C62.1 C63.1 C65.1(INPUT) C65.3(OUTPUT) C66.1(INPUT) C66.3(OUTPUT) C67.1(INPUT) C67.3(OUTPUT) C80.1(INPUT) C80.3(OUTPUT) C81.1 C85.1 C90.1 C94.1 C98.1(INPUT) C98.3(OUTPUT) C99.1(INPUT) C99.3(OUTPUT) C106.1(INPUT) C106.3(OUTPUT) C107.1(INPUT) C107.3(OUTPUT) C118.1(INPUT) C118.3(OUTPUT) C271.1 C292.1 C305.1 C309.1 C310.1 C311.1 C318.1 C320.1 C321.1 C322.1 C328.1 C329.1 C330.1 C331.1 C333.1 C335.1 C336.1 C340.1 C342.1 C343.1 C352.1 C353.1 C357.1 C360.1 C361.1 C364.1 C365.1 C366.1 C367.1 C368.1 C376.1 C517.1 C518.1 C529.1 C530.1 C534.1 C535.1 C537.1 C538.1 FL3.1 FL5.1 FL12.1 FL13.1 FL18.1 FL20.1 FL26.1 FL27.1 L6.2 L7.2 L8.2 L9.2 U9.J10(VDD_CORE#J10) U9.K9(VDD_CORE#K9) U9.K11(VDD_CORE#K11) U9.K13(VDD_CORE#K13) U9.K15(VDD_CORE#K15) U9.K17(VDD_CORE#K17) U9.L10(VDD_CORE#L10) U9.L16(VDD_CORE#L16) U9.L18(VDD_CORE#L18) U9.M15(VDD_CORE#M15) U9.N14(VDD_CORE#N14) U9.N16(VDD_CORE#N16) U9.N18(VDD_CORE#N18) U9.P13(VDD_CORE#P13) U9.P15(VDD_CORE#P15) U9.P17(VDD_CORE#P17) U9.R14(VDD_CORE#R14) U9.R16(VDD_CORE#R16) U9.R18(VDD_CORE#R18) U9.R20(VDD_CORE#R20) U9.T9(VDD_CORE#T9) U9.T15(VDD_CORE#T15) U9.T17(VDD_CORE#T17) U9.U14(VDD_CORE#U14) U9.U16(VDD_CORE#U16) U9.U18(VDD_CORE#U18) U9.V15(VDD_CORE#V15) U9.V17(VDD_CORE#V17) U9.V20(VDD_CORE#V20) U9.W14(VDD_CORE#W14) U29.22(FB_B1)
VDD_CORE_0V8_REG_SW1: L6.1 U29.27(SW_B1A) U29.28(SW_B1B)
VDD_CORE_0V8_REG_SW2: L7.1 U29.15(SW_B2A) U29.16(SW_B2B)
VDD_CORE_0V8_REG_SW3: L8.1 U29.43(SW_B3A) U29.44(SW_B3B)
VDD_CORE_0V8_REG_SW4: L9.1 U29.55(SW_B4A) U29.56(SW_B4B)
VDD_CORE_RAM_0V85: C273.1 C284.1 C297.1 C299.1 C449.1 C450.1 FL21.2 U9.L14(VDDAR_CORE#L14) U9.V13(VDDAR_CORE#V13) U9.V16(VDDAR_CORE#V16) U9.W19(VDDAR_CORE#W19)
VDD_CPU_AVS: C55.1 C56.1 C68.1(INPUT) C68.3(OUTPUT) C69.1(INPUT) C69.3(OUTPUT) C70.1(INPUT) C70.3(OUTPUT) C71.1 C72.1 C73.1 C78.1(INPUT) C78.3(OUTPUT) C79.1 C82.1 C83.1 C84.1(INPUT) C84.3(OUTPUT) C87.1 C91.1(INPUT) C91.3(OUTPUT) C92.1 C93.1(INPUT) C93.3(OUTPUT) C95.1(INPUT) C95.3(OUTPUT) C100.1(INPUT) C100.3(OUTPUT) C294.1 C298.1 C304.1 C308.1 C319.1 C324.1 C327.1 C334.1 C351.1 C499.1 C500.1 C502.1 C504.1 L3.2 L4.2 U9.N10(VDD_CPU#N10) U9.P11(VDD_CPU#P11) U9.R10(VDD_CPU#R10) U9.R12(VDD_CPU#R12) U9.U10(VDD_CPU#U10) U9.V9(VDD_CPU#V9) U9.V11(VDD_CPU#V11) U9.W10(VDD_CPU#W10) U27.22(FB_B1)
VDD_CPU_AVS_REG_SW1: L3.1 U27.27(SW_B1A) U27.28(SW_B1B)
VDD_CPU_AVS_REG_SW2: L4.1 U27.15(SW_B2A) U27.16(SW_B2B)
VDD_CPU_RAM_0V85: C236.1 C237.1 C452.1 C453.1 FL16.2 U9.L11(VDDAR_CPU#L11) U9.W12(VDDAR_CPU#W12)
VDD_DDR_1V1: C101.1 C102.1 C120.1 C128.1 C133.1 C141.1 C149.1(INPUT) C149.3(OUTPUT) C155.1 C156.1 C162.1 C163.1 C164.1 C165.1 C166.1(INPUT) C166.3(OUTPUT) C167.1(INPUT) C167.3(OUTPUT) C168.1(INPUT) C168.3(OUTPUT) C169.1 C177.1 C178.1 C179.1(INPUT) C179.3(OUTPUT) C180.1(INPUT) C180.3(OUTPUT) C181.1(INPUT) C181.3(OUTPUT) C182.1(INPUT) C182.3(OUTPUT) C192.1(INPUT) C192.3(OUTPUT) C193.1(INPUT) C193.3(OUTPUT) C287.1 C290.1 C302.1 C303.1 C316.1 C317.1 C323.1 C326.1 C332.1 C338.1 C339.1 C346.1 C350.1 C356.1 C363.1 C373.1 C374.1 C375.1 C378.1 C381.1 C383.1 C384.1 C387.1 C389.1 C390.1 C391.1 C392.1 C393.1 C395.1 C397.1 C399.1 C494.1 C495.1 L2.2 R180.1 R230.1 R232.1 R239.1 R242.1 R243.1 U9.A1(VDDS_DDR#A1) U9.G8(VDDS_DDR#G8) U9.H7(VDDS_DDR_BIAS#H7) U9.J6(VDDS_DDR_BIAS#J6) U9.J8(VDDS_DDR#J8) U9.K7(VDDS_DDR#K7) U9.L8(VDDS_DDR#L8) U9.M7(VDDS_DDR#M7) U9.M9(VDDS_DDR_C) U9.N8(VDDS_DDR#N8) U9.P7(VDDS_DDR#P7) U9.R6(VDDS_DDR_BIAS#R6) U9.R8(VDDS_DDR#R8) U9.T1(VDDS_DDR#T1) U9.T7(VDDS_DDR_BIAS#T7) U11.A4(VDD2#A4) U11.A9(VDD2#A9) U11.AA3(VDDQ#AA3) U11.AA5(VDDQ#AA5) U11.AA8(VDDQ#AA8) U11.AA10(VDDQ#AA10) U11.AB4(VDD2#AB4) U11.AB9(VDD2#AB9) U11.B3(VDDQ#B3) U11.B5(VDDQ#B5) U11.B8(VDDQ#B8) U11.B10(VDDQ#B10) U11.D1(VDDQ#D1) U11.D5(VDDQ#D5) U11.D8(VDDQ#D8) U11.D12(VDDQ#D12) U11.F3(VDDQ#F3) U11.F5(VDD2#F5) U11.F8(VDD2#F8) U11.F10(VDDQ#F10) U11.H1(VDD2#H1) U11.H5(VDD2#H5) U11.H8(VDD2#H8) U11.H12(VDD2#H12) U11.K1(VDD2#K1) U11.K3(VDD2#K3) U11.K10(VDD2#K10) U11.K12(VDD2#K12) U11.N1(VDD2#N1) U11.N3(VDD2#N3) U11.N10(VDD2#N10) U11.N12(VDD2#N12) U11.R1(VDD2#R1) U11.R5(VDD2#R5) U11.R8(VDD2#R8) U11.R12(VDD2#R12) U11.U3(VDDQ#U3) U11.U5(VDD2#U5) U11.U8(VDD2#U8) U11.U10(VDDQ#U10) U11.W1(VDDQ#W1) U11.W5(VDDQ#W5) U11.W8(VDDQ#W8) U11.W12(VDDQ#W12) U27.50(FB_B4)
VDD_DDR_1V1_REG_SW: L2.1 U27.55(SW_B4A) U27.56(SW_B4B)
VDD_DSI_OSC: C3108.2 FL3026.3(OUT) U3020.1(STANDBY) U3020.4(VDD)
VDD_IO_1V8: C260.1(INPUT) C260.3(OUTPUT) C272.1(INPUT) C272.3(OUTPUT) C276.1 C282.1 C544.1 C1242.1 C1249.1 C3049.1 FL3011.1 R1188.1 R1189.1 R1190.1 R1191.1 R1192.2 R1196.1 R1197.1 R1198.1 R1200.1 R1201.1 R1204.1 U9.AA8(VDDS_MMC0#AA8) U9.AB7(VDDS_MMC0#AB7) U9.Y7(VDDS_MMC0#Y7) U29.9(VOUT_LDO3) U1017.H3(VCCQ.1) U1017.H8(VCCQ.2) U1017.L2(VCCQ.3) U1017.L4(VCCQ.4) U1017.L7(VCCQ.5) U1017.L9(VCCQ.6) U1017.P3(VCCQ.7) U1017.P8(VCCQ.8)
VDD_IO_3V3: C32.1(INPUT) C32.3(OUTPUT) C33.1(INPUT) C33.3(OUTPUT) C37.1(INPUT) C37.3(OUTPUT) C38.1(INPUT) C38.3(OUTPUT) C64.1(INPUT) C64.3(OUTPUT) C96.1 C97.1 C252.1 C253.1 C254.1 C255.1 C256.1 C257.1 C258.1 C259.1 C262.1 C263.1 C264.1 C265.1 C266.1 C267.1 C268.1 C269.1 C270.1 C274.1 C275.1 C277.1 C280.1 C283.1 C285.1 C1198.1 C1209.2 C1240.1 C1241.1 C1245.2 C2084.1 C2120.1 C3105.1 C3106.1 C3107.1 C3109.2 FL3026.1(IN) L2004.2 L2008.1 R20.1 R23.1 R25.1 R27.1 R37.1 R38.1 R43.2 R54.1 R66.1 R79.1 R81.1 R86.1 R1001.2 R1002.2 R1134.1 R1219.1 R2020.1 R2021.1 R2099.1 R2111.1 R2112.2 R2113.2 R2114.2 R2116.2 R3061.2 R3114.1 RJ1000.1 U6.7(VOUT1) U6.8(VOUT2) U9.AA17(VDDSHV2#AA17) U9.AA19(VDDSHV1#AA19) U9.AA20(VDDSHV1#AA20) U9.AA21(VDDSHV4#AA21) U9.AB16(VDDSHV2#AB16) U9.AB18(VDDSHV2#AB18) U9.AC17(VDDSHV2#AC17) U9.AC19(VDDSHV1#AC19) U9.AC20(VDDSHV1#AC20) U9.U8(VDDSHV0#U8) U9.U20(VDDSHV6#U20) U9.U22(VDDSHV6#U22) U9.V7(VDDSHV0#V7) U9.V21(VDDSHV3#V21) U9.W22(VDDSHV3#W22) U9.Y22(VDDSHV4#Y22) U1002.9(VIN) U1011.8(VCC) U1017.F2(VCC.1) U1017.F3(VCC.2) U1017.F4(VCC.3) U1017.F5(VCC.4) U1017.F6(VCC.5) U1017.F7(VCC.6) U1017.F8(VCC.7) U1017.F9(VCC.8) U1033.5(VCC) U2007.5(VIO) U2023.3(EN) U2023.4(BIAS) U2023.6(IN) U3019.16(VDDIO#16) U3019.33(VDDIO#33) U3022.16(VDDIO)
VDD_MCU_0V85: C157.1 C158.1 C159.1 C160.1(INPUT) C160.3(OUTPUT) C184.1(INPUT) C184.3(OUTPUT) C197.1(INPUT) C197.3(OUTPUT) C198.1(INPUT) C198.3(OUTPUT) C337.1 C344.1 C354.1 C355.1 C358.1 C482.1 C483.1 FL9.1 L1.2 U9.L20(VDD_MCU#L20) U9.M19(VDD_MCU#M19) U9.M21(VDD_MCU#M21) U9.N20(VDD_MCU#N20) U9.P19(VDD_MCU#P19) U27.49(FB_B3)
VDD_MCU_0V85_REG_SW: L1.1 U27.43(SW_B3A) U27.44(SW_B3B)
VDD_MCU_RAM_0V85: C121.1 C130.1 C451.1 FL9.2 U9.K19(VDDAR_MCU#K19) U9.T19(VDDAR_MCU#T19)
VDD_MCUIO_1V8: C161.1(INPUT) C161.3(OUTPUT) C173.1 C205.1 C206.1 C371.1 C380.1 C396.1 C413.1 C513.1 R114.2 R144.1 R149.1 R150.1 R151.1 R153.2 R154.1 R156.1 R158.1 R161.1 R162.1 R3138.2 R3139.2 R3140.2 U9.H19(VDDSHV1_MCU#H19) U9.H21(VDDSHV1_MCU#H21) U9.J20(VDDSHV1_MCU#J20) U18.5(VCC) U24.B4(VCC#B4) U24.D1(VCC#D1) U24.E4(VCC#E4) U27.11(VOUT_LDO2)
VDD_MCUIO_3V3: C119.1(INPUT) C119.3(OUTPUT) C208.1 C211.1 C359.1 C362.1 C382.1 C496.1 C536.1 R74.1 R105.1 R106.1 R115.2 R121.1 R273.2 R1206.1 R1207.1 R1208.1 R1209.1 R3143.1 R3145.2 U9.J22(VDDSHV2_MCU#J22) U9.K21(VDDSHV2_MCU#K21) U9.L22(VDDSHV0_MCU#L22) U9.M22(VDDSHV0_MCU#M22) U22.7(VOUT1) U22.8(VOUT2) U27.48(VIO_IN) U29.48(VIO_IN)
VDD_PHYIO_1V8: C261.1 C507.1 C508.1 FL1.1 FL4.1 FL11.1 FL14.1 FL19.1 FL28.1 L5.2 U9.W7(VDDA_1P8_MLB) U27.37(FB_B5)
VDD_PHYIO_1V8_REG_SW: L5.1 U27.34(SW_B5A)
VDD_RAM_0V85: C539.1 C540.1 FL16.1 FL21.1 L10.2 U29.37(FB_B5)
VDD_RAM_0V85_REG_SW: L10.1 U29.34(SW_B5A)
VDD_SD_DV: C315.1 C546.1 U9.T20(VDDSHV5#T20) U9.T22(VDDSHV5#T22) U29.13(VOUT_LDO1)
VDDA_0P8_CSIRX: C404.1 C405.1 C446.1 FL27.2 U9.H17(VDDA_0P8_CSIRX)
VDDA_0P8_DLL_MMC0: C49.1 C50.1 C430.1 FL6.2 U9.Y9(VDDA_0P8_DLL_MMC0)
VDDA_0P8_DP: C402.1 C403.1 C438.1 C439.1 FL26.2 U9.G12(VDDA_0P8_DP#G12) U9.J12(VDDA_0P8_DP#J12)
VDDA_0P8_DP_C: C189.1 C190.1 C440.1 C441.1 FL13.2 U9.G14(VDDA_0P8_DP_C#G14) U9.H13(VDDA_0P8_DP_C#H13)
VDDA_0P8_DSITX: C187.1 C188.1 C442.1 FL12.2 U9.H15(VDDA_0P8_DSITX) U9.J16(VDDA_0P8_DSITX_C)
VDDA_0P8_PLL_DDR: C201.1 C202.1 C427.1 FL15.2 U9.N9(VDDA_0P8_PLL_DDR)
VDDA_0P8_PLL_MLB: C286.1 C570.1 C571.1 FL29.2 U9.W8(VDDA_0P8_PLL_MLB)
VDDA_0P8_SERDES: C246.1 C247.1 C431.1 C432.1 C433.1 FL20.2 U9.AA12(VDDA_0P8_SERDES2_3#AA12) U9.AA15(VDDA_0P8_SERDES0_1#AA15) U9.Y11(VDDA_0P8_SERDES2_3#Y11) U9.Y13(VDDA_0P8_SERDES2_3#Y13) U9.Y14(VDDA_0P8_SERDES0_1#Y14) U9.Y16(VDDA_0P8_SERDES0_1#Y16)
VDDA_0P8_SERDES_C: C43.1 C44.1 C435.1 C436.1 FL3.2 U9.AB12(VDDA_0P8_SERDES_C2_3#AB12) U9.AB13(VDDA_0P8_SERDES_C2_3#AB13) U9.AB14(VDDA_0P8_SERDES_C0_1#AB14) U9.AB15(VDDA_0P8_SERDES_C0_1#AB15)
VDDA_0P8_UFS: C242.1 C243.1 FL18.2 U9.AB9(VDDA_0P8_UFS)
VDDA_0P8_USB: C47.1 C48.1 FL5.2 U9.AA10(VDDA_0P8_USB)
VDDA_1P8_CSI_RX: C185.1 C186.1 C434.1 FL11.2 U9.G16(VDDA_1P8_CSIRX)
VDDA_1P8_DP: C199.1 C200.1 C437.1 FL14.2 U9.H11(VDDA_1P8_DP)
VDDA_1P8_DSITX: C410.1 C411.1 FL28.2 U9.J14(VDDA_1P8_DSITX)
VDDA_1P8_SERDES: C30.1 C31.1 C444.1 C445.1 FL1.2 U9.AC11(VDDA_1P8_SERDES2_3#AC11) U9.AC12(VDDA_1P8_SERDES2_3#AC12) U9.AC14(VDDA_1P8_SERDES0_1#AC14) U9.AC15(VDDA_1P8_SERDES0_1#AC15)
VDDA_1P8_UFS: C244.1 C245.1 FL19.2 U9.AC8(VDDA_1P8_UFS)
VDDA_1P8_USB: C45.1 C46.1 C443.1 FL4.2 U9.AC9(VDDA_1P8_USB)
VDDA_LM5141: C1051.1 R1027.2 R1028.2 R1146.2 U1007.2(VDDA)
VDDA_TC811: C2037.1 C2125.1 C2128.1 C2129.1 L2008.2 U2011.11(VDDA)
VDDHS11_DSI: C3057.1 C3067.1 C3068.1 C3069.1 C3070.1 C3071.1 C3098.1 FL3012.2 U3019.12(VDD11_A) U3019.21(VDD11_HS1) U3019.25(VDD11_S) U3019.28(VDD11_HS0) U3019.64(VDD11_DSI)
VDDI_MMC2: C1238.1 C1239.1 U1017.E4(VDDIM)
VDDIO_TC811: C2023.1 C2117.1 C2118.1 C2119.1 C2122.1 C2123.1 C2124.1 L2004.1 R2026.2 U2011.22(VDDIO)
VDDL11_DSI: C3062.1 C3101.1 C3102.1 C3103.1 FL3014.2 U3019.9(VDD11_L#9) U3019.42(VDD11_L#42)
VDDP11_DSI: C3058.1 C3096.1 C3097.1 C3110.1 FL3013.2 U3019.17(VDD11_P0) U3019.50(VDD11_P1)
VINT_LEOA_1V8: C509.1 R280.1 U27.2(VOUT_LDOVINT)
VINT_LEOB_1V8: C541.1 U29.2(VOUT_LDOVINT)
AUDIO_EXT_REFCLK1/MCAN4_TX: TPX122.1 U9.AE20(PRG1_PRU0_GPO7)
BOOT_EEPROM_WP: TPX275.1 U9.F25(WKUP_GPIO0_1)
C_AUDIO_EXT_REFCLK2: TPX182.1 U9.W26(RGMII6_RXC)
C_DP0_AUX_N: C415.1 U9.G6(DP0_AUXN)
C_DP0_AUX_P: C414.1 U9.F7(DP0_AUXP)
C_DP0_TX0_N: C422.1 U9.B11(SERDES4_TX0_N)
C_DP0_TX0_P: C423.1 U9.A12(SERDES4_TX0_P)
C_DP0_TX1_N: C420.1 U9.B10(SERDES4_TX1_N)
C_DP0_TX1_P: C421.1 U9.A11(SERDES4_TX1_P)
C_DP0_TX2_N: C418.1 U9.B8(SERDES4_TX2_N)
C_DP0_TX2_P: C419.1 U9.A9(SERDES4_TX2_P)
C_DP0_TX3_N: C416.1 U9.B7(SERDES4_TX3_N)
C_DP0_TX3_P: C417.1 U9.A8(SERDES4_TX3_P)
C_MCASP10_ACLKR: TPX185.1 U9.Y28(RGMII6_TX_CTL)
C_MCASP10_AFSR: TPX11.1 U9.V23(RGMII6_RX_CTL)
C_MCASP10_AXR4: TPX36.1 U9.V25(RGMII6_TD1)
C_MCASP10_AXR5: TPX60.1 U9.W27(RGMII6_TD0)
C_MCASP10_AXR6: TPX84.1 U9.W29(RGMII6_TXC)
C_MCASP11_AXR4: TPX12.1 U9.Y29(RGMII6_RD3)
C_MCASP11_AXR5: TPX135.1 U9.Y27(RGMII6_RD2)
C_MCASP11_AXR6: TPX37.1 U9.W24(RGMII6_RD1)
C_MCASP11_AXR7: TPX109.1 U9.W25(RGMII6_RD0)
C_PCIE0_TX0_N: C227.1 U9.AF19(SERDES0_TX0_N)
C_PCIE0_TX0_P: C226.1 U9.AG18(SERDES0_TX0_P)
C_PCIE1_TX0_N: C224.1 U9.AF15(SERDES1_TX0_N)
C_PCIE1_TX0_P: C225.1 U9.AG14(SERDES1_TX0_P)
C_PCIE1_TX1_N: C223.1 U9.AF16(SERDES1_TX1_N)
C_PCIE1_TX1_P: C222.1 U9.AG15(SERDES1_TX1_P)
C_PCIE2_TX0_N: C213.1 U9.AF13(SERDES2_TX0_N)
C_PCIE2_TX0_P: C212.1 U9.AG12(SERDES2_TX0_P)
C_PCIE2_TX1_N: C221.1 U9.AF12(SERDES2_TX1_N)
C_PCIE2_TX1_P: C220.1 U9.AG11(SERDES2_TX1_P)
C_SGMII2_TX0_N: C215.1 U9.AF18(SERDES0_TX1_N)
C_SGMII2_TX0_P: C214.1 U9.AG17(SERDES0_TX1_P)
C_UART4_RXD: TPX41.1 U9.W23(RGMII6_TD3)
C_UART4_TXD: TPX81.1 U9.W28(RGMII6_TD2)
C_UB981_DOUT0_N: C3121.1 U3019.26(DOUT0-)
C_UB981_DOUT0_P: C3119.1 U3019.27(DOUT0+)
C_USB_SS_TX1_N: C219.1 U9.AF10(SERDES3_TX1_N)
C_USB_SS_TX1_P: C218.1 U9.AG9(SERDES3_TX1_P)
C_USB_SS_TX2_N: C217.1 U9.AF9(SERDES3_TX0_N)
C_USB_SS_TX2_P: C216.1 U9.AG8(SERDES3_TX0_P)
CAM_0_N: C3125.1 U3022.51(RIN0-)
CAM_0_P: C3124.1 U3022.50(RIN0+)
CAM_1_N: C3132.1 U3022.54(RIN1-)
CAM_1_P: C3131.1 U3022.53(RIN1+)
CAM_2_N: C3138.1 U3022.60(RIN2-)
CAM_2_P: C3137.1 U3022.59(RIN2+)
CAM_3_N: C3144.1 U3022.63(RIN3-)
CAM_3_P: C3143.1 U3022.62(RIN3+)
CAN_POWER_ON_HV: R2106.1
CAN_WAKE: JZ2000.10 R2008.1 R2101.2 RJ2008.2
CAN_WKUP: TPX299.1 U27.47(GPIO4)
CANH_1: JZ2000.4 R2098.1 U2007.13(CANH)
CANL_1: JZ2000.3 R2104.2 U2007.12(CANL)
CLK1X_A: C1071.1
CLK2X_B: R1032.2 R1146.1 U1007.1(DEMB)
CLK8X_A: RJ1001.1
CLK8X_A_10V5: RJ1013.3
CLK8X_B: RJ1001.3
CLK8X_B_10V5: RJ1013.1
CLKGEN_USB_REFCLK_N: TPX429.1 U9.AE9(PCIE_REFCLK3N)
CLKGEN_USB_REFCLK_P: TPX428.1 U9.AD10(PCIE_REFCLK3P)
CON_DP0_AUX_N: D3029.1(I/O) FL3015.3 J3003.17(AUX_CH_N) R3061.1
CON_DP0_AUX_P: D3030.1(I/O) FL3015.2 J3003.15(AUX_CH_P) R3062.2
CON_DP0_TX0_N: D3033.1(I/O) FL3024.3 J3003.3(ML_L0_N)
CON_DP0_TX0_P: D3034.1(I/O) FL3024.2 J3003.1(ML_L0_P)
CON_DP0_TX1_N: D3021.1(I/O) FL3020.3 J3003.6(ML_L1_N)
CON_DP0_TX1_P: D3022.1(I/O) FL3020.2 J3003.4(ML_L1_P)
CON_DP0_TX2_N: D3031.1(I/O) FL3023.3 J3003.9(ML_L2_N)
CON_DP0_TX2_P: D3032.1(I/O) FL3023.2 J3003.7(ML_L2_P)
CON_DP0_TX3_N: D3019.1(I/O) FL3019.3 J3003.12(ML_L3_N)
CON_DP0_TX3_P: D3020.1(I/O) FL3019.2 J3003.10(ML_L3_P)
CONN_USB1_DM: FL1001.2 J1000.2(D-)
CONN_USB1_DP: FL1001.3 J1000.3(D+)
CONN_USB2_DM: FL1000.3 J1001.2(D-)
CONN_USB2_DP: FL1000.2 J1001.3(D+)
CONN_USB_RXN0: FL1002.3 J1000.5(STDA_SSRX-) U1000.5(D2-) U1000.6(NC6)
CONN_USB_RXN1: FL3028.3 J1001.5(STDA_SSRX-) U3021.5(D2-) U3021.6(NC6)
CONN_USB_RXP0: FL1002.2 J1000.6(STDA_SSRX+) U1000.4(D2+) U1000.7(NC7)
CONN_USB_RXP1: FL3028.2 J1001.6(STDA_SSRX+) U3021.4(D2+) U3021.7(NC7)
CONN_USB_TXN0: FL1003.3 J1000.8(STDA_SSTX-) U1000.2(D1-) U1000.9(NC9)
CONN_USB_TXN1: FL3029.3 J1001.8(STDA_SSTX-) U3021.2(D1-) U3021.9(NC9)
CONN_USB_TXP0: FL1003.2 J1000.9(STDA_SSTX+) U1000.1(D1+) U1000.10(NC10)
CONN_USB_TXP1: FL3029.2 J1001.9(STDA_SSTX+) U3021.1(D1+) U3021.10(NC10)
CS_P: C1200.1 Q1003.1(S) Q1004.1(S) R1019.1 R1031.2
CSI0_RX0_N: U9.B19(CSI0_RXN0) U3022.24(CSI0_D0-)
CSI0_RX0_P: U9.A20(CSI0_RXP0) U3022.25(CSI0_D0+)
CSI0_RX1_N: U9.D18(CSI0_RXN1) U3022.26(CSI0_D1-)
CSI0_RX1_P: U9.C19(CSI0_RXP1) U3022.27(CSI0_D1+)
CSI0_RX2_N: U9.D17(CSI0_RXN2) U3022.28(CSI0_D2-)
CSI0_RX2_P: U9.C18(CSI0_RXP2) U3022.29(CSI0_D2+)
CSI0_RX3_N: U9.E16(CSI0_RXN3) U3022.30(CSI0_D3-)
CSI0_RX3_P: U9.E17(CSI0_RXP3) U3022.31(CSI0_D3+)
CSI0_RXCLK_N: U9.B20(CSI0_RXCLKN) U3022.22(CSI0_CLK-)
CSI0_RXCLK_P: U9.A21(CSI0_RXCLKP) U3022.23(CSI0_CLK+)
CSI0_RXRCALIB: R238.1 U9.F16(CSI0_RXRCALIB)
CSI1_RX0_N: TPX327.1 U9.B16(CSI1_RXN0)
CSI1_RX0_P: TPX328.1 U9.A17(CSI1_RXP0)
CSI1_RX1_N: TPX239.1 U9.D15(CSI1_RXN1)
CSI1_RX1_P: TPX240.1 U9.C16(CSI1_RXP1)
CSI1_RX2_N: TPX368.1 U9.D14(CSI1_RXN2)
CSI1_RX2_P: TPX369.1 U9.C15(CSI1_RXP2)
CSI1_RX3_N: TPX283.1 U9.E13(CSI1_RXN3)
CSI1_RX3_P: TPX284.1 U9.E14(CSI1_RXP3)
CSI1_RXCLK_N: TPX347.1 U9.B17(CSI1_RXCLKN)
CSI1_RXCLK_P: TPX348.1 U9.A18(CSI1_RXCLKP)
CSI1_RXRCALIB: R234.1 U9.F15(CSI1_RXRCALIB)
CSI2_EXP_A_GPIO2: TPX138.1 U9.T27(MMC2_DAT1)
CSI2_EXP_A_GPIO4: TPX16.1 U9.T24(MMC2_DAT0)
DDR0_CAL0: R233.1 U9.H2(DDR0_CAL0)
DP0_AUX_N: C415.2 FL3015.4
DP0_AUX_P: C414.2 FL3015.1
DP0_CONFIG1: J3003.13(CONFIG1) R3118.1
DP0_CONFIG2: J3003.14(CONFIG2) R3119.1
DP0_HPD: J3003.18(HPD) R3121.2
DP0_HPD/PRG1_IEP0_EDIO_OUTVALID: TPX205.1 U9.Y4(SPI0_CS1)
DP0_TX0_N: C422.2 FL3024.4
DP0_TX0_P: C423.2 FL3024.1
DP0_TX1_N: C420.2 FL3020.4
DP0_TX1_P: C421.2 FL3020.1
DP0_TX2_N: C418.2 FL3023.4
DP0_TX2_P: C419.2 FL3023.1
DP0_TX3_N: C416.2 FL3019.4
DP0_TX3_P: C417.2 FL3019.1
DSI0_TX0_N: U9.D11(DSI_TXN0) U3019.57(DSI0_D0N)
DSI0_TX0_P: U9.C12(DSI_TXP0) U3019.58(DSI0_D0P)
DSI0_TX1_N: U9.D12(DSI_TXN1) U3019.55(DSI0_D1N)
DSI0_TX1_P: U9.C13(DSI_TXP1) U3019.56(DSI0_D1P)
DSI0_TX2_N: U9.B13(DSI_TXN2) U3019.53(DSI0_D2N)
DSI0_TX2_P: U9.A14(DSI_TXP2) U3019.54(DSI0_D2P)
DSI0_TX3_N: U9.B14(DSI_TXN3) U3019.51(DSI0_D3N)
DSI0_TX3_P: U9.A15(DSI_TXP3) U3019.52(DSI0_D3P)
DSI0_TXCLK_N: U9.E10(DSI_TXCLKN) U3019.59(DSI0_CLKN)
DSI0_TXCLK_P: U9.E11(DSI_TXCLKP) U3019.60(DSI0_CLKP)
DSI_CL: R3059.1 U3011.13(CL)
DSI_DIAG_EN: R3058.1 U3011.12(DIAG_EN)
DSI_REFCLK_3V3: R3102.1
DSI_TX_CALIB: R237.1 U9.F12(DSI_TXRCALIB)
DSI_UB981_INTB: R3105.2 R3115.2 U9.V5(TIMER_IO1)
EMU_RSTN: J1011.6(NRESET)
EN_3V3IO_LDSW: Q13.G R46.2 U6.3(ON) U29.53(GPIO11)
EN_DDR0V6_BUCK: U29.46(GPIO3)
EN_DRV_OUT: TP105.1(TP) TPX279.1 U27.29(EN_DRV)
EN_MCU3V3_LDSW: R277.1 R515.2 U22.3(ON)
ENET_EN: R2114.1 U2011.7(EN)
ENET_EXP_INTB: TPX164.1 U9.R28(MMC1_SDWP)
ENET_INH: R2112.1 U2011.10(INH)
ENET_INTSN: R2115.1 R2116.1
ENET_RSTN: U2011.3(RESET_N)
ENET_WAKE: R2113.1 U2011.8(WAKE)
EXT_TDI: J1011.5(TDI) U131.2(I)
EXT_TDO: J1011.4(TDO) U130.4(O)
EXT_TMS: J1011.2(TMS) U129.2(I)
FB: R1035.1 R1041.2 U1008.11(FB)
FB_5141: R1024.1 R1025.2 U1007.19(FB)
FPD_DOUT0_N: FL3030.3 J3005.3
FPD_DOUT0_P: FL3030.2 J3005.1
G720_VDD1A: R2059.1 U2011.9(NC9)
G720_VDD1B: R2058.1 U2011.21(NC21)
G720_VDDIO: R2026.1 U2011.34(TX_ER)
GPIO0_6: TPX323.1 U9.AD20(PRG1_PRU0_GPO5)
GPIO0_61: TPX59.1 U9.AB29(PRG0_PRU0_GPO18)
GPIO0_78/PRG0_RGMII2_TX_CTL: TPX32.1 U9.AF29(PRG0_PRU1_GPO15)
GPIO0_79/PRG0_RGMII2_TXC: TPX56.1 U9.AG29(PRG0_PRU1_GPO16)
GPIO0_127/EQEP0_S/MLB0_MLBCLK: TPX204.1 U9.AC4(UART1_CTSN)
GPIO1_0/EQEP0_I/MLB0_MLBDAT: TPX243.1 U9.AD5(UART1_RTSN)
GPIO1_11/MAIN_I3C0_SDAPULLEN: TPX256.1 U9.U2(ECAP0_IN_APWM_OUT)
GPIO1_12/MLB0_REFCLK: TPX229.1 U9.U3(EXT_REFCLK1)
GPIO1_23/UART9_RXD: TPX188.1 U9.T28(MMC2_DAT3)
GPIO1_24/UART9_TXD: TPX113.1 U9.T29(MMC2_DAT2)
GPIO_MCU_RGMII1_RST#: TPX17.1 U9.F27(WKUP_GPIO0_3)
H_DDR_RET_1V1: R180.2 U9.P6(DDR_RET) U29.47(GPIO4)
H_I3C0_SCL: TPX255.1 U9.W2(I3C0_SCL)
H_I3C0_SDA: TPX301.1 U9.W1(I3C0_SDA)
H_MCU_INT#: R93.2 R273.1 U27.14(NINT) U29.14(NINT)
H_MCU_PORZ: R272.1 TPX295.1 U27.25(NRSTOUT)
H_MDIO_D: R2111.2
H_RGMII0_RXD1: R2020.2
H_RGMII0_RXD2: R2021.2
H_SOC_PORZ: R493.1 TPX234.1 U27.53(GPIO11)
H_WKUP_LFOSC0_XI: R281.2 R504.1 R3145.1 R3146.2
HDRV1_N: C1049.2 L1001.1 Q1003.5(D) Q1005.1(S) U1008.28(SW1)
HDRV1_P: R1014.2 U1008.27(HDRV1)
HDRV2_N: C1046.1 D1003.2(ANODE) D1006.1(CATHODE) L1001.2 Q1004.5(D) Q1006.1(S) U1008.18(SW2)
HDRV2_P: R1015.1 U1008.19(HDRV2)
I2C0_SCL: R20.2 TPX265.1 U9.AC5(I2C0_SCL)
I2C0_SDA: R23.2 TPX291.1 U9.AA5(I2C0_SDA)
I2C1_SCL: R37.2 U9.Y6(I2C1_SCL) U3019.47(I2C_SCL)
I2C1_SDA: R38.2 U9.AA6(I2C1_SDA) U3019.48(I2C_SDA)
I2C3_SCL: R81.2 TPX112.1 U9.T26(MMC2_CLK)
I2C3_SDA: R79.2 TPX163.1 U9.T25(MMC2_CMD)
I2C6_SCL: R27.2 TPX292.1 U9.AA3(SPI0_D1)
I2C6_SDA: R66.2 TPX460.1 U9.Y2(SPI1_D1)
LDRV1: R1020.2 U1008.25(LDRV1)
LDRV2: R1021.1 U1008.21(LDRV2)
LEOA_GPIO3: R276.2 R277.2 U27.46(GPIO3)
LEOA_GPIO8: R504.2 U27.41(GPIO8)
LEOA_GPIO9: R522.2 U27.19(GPIO9)
LEOA_GPIO10: R502.2 U27.42(GPIO10)
LEOA_OSC32KCAP: C505.1 U27.40(OSC32KCAP)
LEOA_OSC32KIN: C503.2 U27.38(OSC32KIN) Y6.2
LEOA_OSC32KOUT: C506.2 U27.39(OSC32KOUT) Y6.1
LEOA_SCLK: U27.23(GPIO5) U29.23(GPIO5)
LEOA_SDATA: U27.24(GPIO6) U29.24(GPIO6)
LEOB_GPIO1: R287.2 U29.32(GPIO1)
LEOB_GPIO1_RES: R287.1 TP108.1(TP)
LEOB_GPIO2: R288.2 U29.33(GPIO2)
LEOB_GPIO2_RES: R288.1 TP109.1(TP)
LEOB_GPIO7: R494.2 U29.18(GPIO7)
LEOB_GPIO7_RES: R494.1 TP3016.1(TP)
LEOB_GPIO8: R495.2 U29.41(GPIO8)
LEOB_GPIO8_RES: R495.1 TP3017.1(TP)
LEOB_GPIO9: R496.2 U29.19(GPIO9)
LEOB_GPIO9_RES: R496.1 TP3018.1(TP)
LEOB_GPIO10: R503.1 U29.42(GPIO10)
LEOB_GPIO10_RES: R503.2 TP115.1(TP)
LFDSI: C3056.1 U3019.49(LFDSI)
LFT: C3114.1 U3019.20(LFT)
LPDDR4_CA0: U9.G4(DDR0_CA0) U11.H2(CA0_A) U11.R2(CA0_B)
LPDDR4_CA1: U9.H3(DDR0_CA1) U11.J2(CA1_A) U11.P2(CA1_B)
LPDDR4_CA2: U9.K5(DDR0_CA2) U11.H9(CA2_A) U11.R9(CA2_B)
LPDDR4_CA3: U9.J4(DDR0_CA3) U11.H10(CA3_A) U11.R10(CA3_B)
LPDDR4_CA4: U9.K2(DDR0_CA4) U11.H11(CA4_A) U11.R11(CA4_B)
LPDDR4_CA5: U9.H5(DDR0_CA5) U11.J11(CA5_A) U11.P11(CA5_B)
LPDDR4_CK_C: U9.J1(DDR0_CKN) U11.J9(CK_C_A) U11.P9(CK_C_B)
LPDDR4_CK_T: U9.H1(DDR0_CKP) U11.J8(CK_T_A) U11.P8(CK_T_B)
LPDDR4_CKE0: U9.G3(DDR0_CKE0) U11.J4(CKE0_A) U11.P4(CKE0_B)
LPDDR4_CKE1: U9.J3(DDR0_CKE1) U11.J5(CKE1_A) U11.P5(CKE1_B)
LPDDR4_CSN0_0: U9.J5(DDR0_CSN0_0) U11.H4(CS0_A)
LPDDR4_CSN0_1: U9.K3(DDR0_CSN0_1) U11.R4(CS0_B)
LPDDR4_CSN1_0: U9.G5(DDR0_CSN1_0) U11.H3(CS1_A)
LPDDR4_CSN1_1: U9.J2(DDR0_CSN1_1) U11.R3(CS1_B)
LPDDR4_DM0_DBI0#: U9.A3(DDR0_DM0) U11.C3(DMI0_A)
LPDDR4_DM1_DBI1#: U9.E4(DDR0_DM1) U11.C10(DMI1_A)
LPDDR4_DM2_DBI2#: U9.N1(DDR0_DM2) U11.Y3(DMI0_B)
LPDDR4_DM3_DBI3#: U9.R5(DDR0_DM3) U11.Y10(DMI1_B)
LPDDR4_DQ0: U9.A5(DDR0_DQ0) U11.B2(DQ0_A)
LPDDR4_DQ1: U9.A6(DDR0_DQ1) U11.C2(DQ1_A)
LPDDR4_DQ2: U9.B5(DDR0_DQ2) U11.E2(DQ2_A)
LPDDR4_DQ3: U9.C2(DDR0_DQ3) U11.F2(DQ3_A)
LPDDR4_DQ4: U9.B4(DDR0_DQ4) U11.F4(DQ4_A)
LPDDR4_DQ5: U9.C3(DDR0_DQ5) U11.E4(DQ5_A)
LPDDR4_DQ6: U9.A2(DDR0_DQ6) U11.C4(DQ6_A)
LPDDR4_DQ7: U9.A4(DDR0_DQ7) U11.B4(DQ7_A)
LPDDR4_DQ8: U9.D1(DDR0_DQ8) U11.B11(DQ8_A)
LPDDR4_DQ9: U9.C4(DDR0_DQ9) U11.C11(DQ9_A)
LPDDR4_DQ10: U9.F1(DDR0_DQ10) U11.E11(DQ10_A)
LPDDR4_DQ11: U9.G2(DDR0_DQ11) U11.F11(DQ11_A)
LPDDR4_DQ12: U9.F2(DDR0_DQ12) U11.F9(DQ12_A)
LPDDR4_DQ13: U9.F3(DDR0_DQ13) U11.E9(DQ13_A)
LPDDR4_DQ14: U9.D3(DDR0_DQ14) U11.C9(DQ14_A)
LPDDR4_DQ15: U9.F5(DDR0_DQ15) U11.B9(DQ15_A)
LPDDR4_DQ16: U9.L5(DDR0_DQ16) U11.AA2(DQ0_B)
LPDDR4_DQ17: U9.M5(DDR0_DQ17) U11.Y2(DQ1_B)
LPDDR4_DQ18: U9.N5(DDR0_DQ18) U11.V2(DQ2_B)
LPDDR4_DQ19: U9.L4(DDR0_DQ19) U11.U2(DQ3_B)
LPDDR4_DQ20: U9.L2(DDR0_DQ20) U11.U4(DQ4_B)
LPDDR4_DQ21: U9.L1(DDR0_DQ21) U11.V4(DQ5_B)
LPDDR4_DQ22: U9.N2(DDR0_DQ22) U11.Y4(DQ6_B)
LPDDR4_DQ23: U9.N4(DDR0_DQ23) U11.AA4(DQ7_B)
LPDDR4_DQ24: U9.T3(DDR0_DQ24) U11.AA11(DQ8_B)
LPDDR4_DQ25: U9.T2(DDR0_DQ25) U11.Y11(DQ9_B)
LPDDR4_DQ26: U9.P2(DDR0_DQ26) U11.V11(DQ10_B)
LPDDR4_DQ27: U9.P3(DDR0_DQ27) U11.U11(DQ11_B)
LPDDR4_DQ28: U9.P5(DDR0_DQ28) U11.U9(DQ12_B)
LPDDR4_DQ29: U9.R4(DDR0_DQ29) U11.V9(DQ13_B)
LPDDR4_DQ30: U9.T4(DDR0_DQ30) U11.Y9(DQ14_B)
LPDDR4_DQ31: U9.T5(DDR0_DQ31) U11.AA9(DQ15_B)
LPDDR4_DQS0_N: U9.B1(DDR0_DQS0N) U11.E3(DQS0_C_A)
LPDDR4_DQS0_P: U9.B2(DDR0_DQS0P) U11.D3(DQS0_T_A)
LPDDR4_DQS1_N: U9.E2(DDR0_DQS1N) U11.E10(DQS1_C_A)
LPDDR4_DQS1_P: U9.E3(DDR0_DQS1P) U11.D10(DQS1_T_A)
LPDDR4_DQS2_N: U9.M2(DDR0_DQS2N) U11.V3(DQS0_C_B)
LPDDR4_DQS2_P: U9.M3(DDR0_DQS2P) U11.W3(DQS0_T_B)
LPDDR4_DQS3_N: U9.R1(DDR0_DQS3N) U11.V10(DQS1_C_B)
LPDDR4_DQS3_P: U9.R2(DDR0_DQS3P) U11.W10(DQS1_T_B)
LPDDR4_ODT_CA_A: R235.1 R239.2 U11.G2(ODT_CA_A)
LPDDR4_ODT_CA_B: R227.1 R230.2 U11.T2(ODT_CA_B)
LPDDR4_RST#: R228.1 R232.2 U9.K6(DDR0_RESETN) U11.T11(RESET_N)
LPDDR4_ZQ0: R242.2 U11.A5(ZQ0)
LPDDR4_ZQ1: R243.2 U11.A8(ZQ1)
LS2_CT: C89.1 U6.6(CT)
LS3_CT: C204.1 U22.6(CT)
MCAN0_RX: TPX270.1 U9.W5(MCAN0_RX)
MCAN0_TX: TPX293.1 U9.W6(MCAN0_TX)
MCAN2_RX/MLB0_MLBSIG: TPX222.1 U9.AC2(UART0_CTSN)
MCAN2_TX/MLB_INT#: TPX357.1 U9.AB1(UART0_RTSN)
MCAN_EN: R2108.1
MCAN_NFAULT: R2100.1
MCASP0_ACLKX/SPI3_CS1: TPX157.1 U9.AB26(PRG0_PRU0_GPO9)
